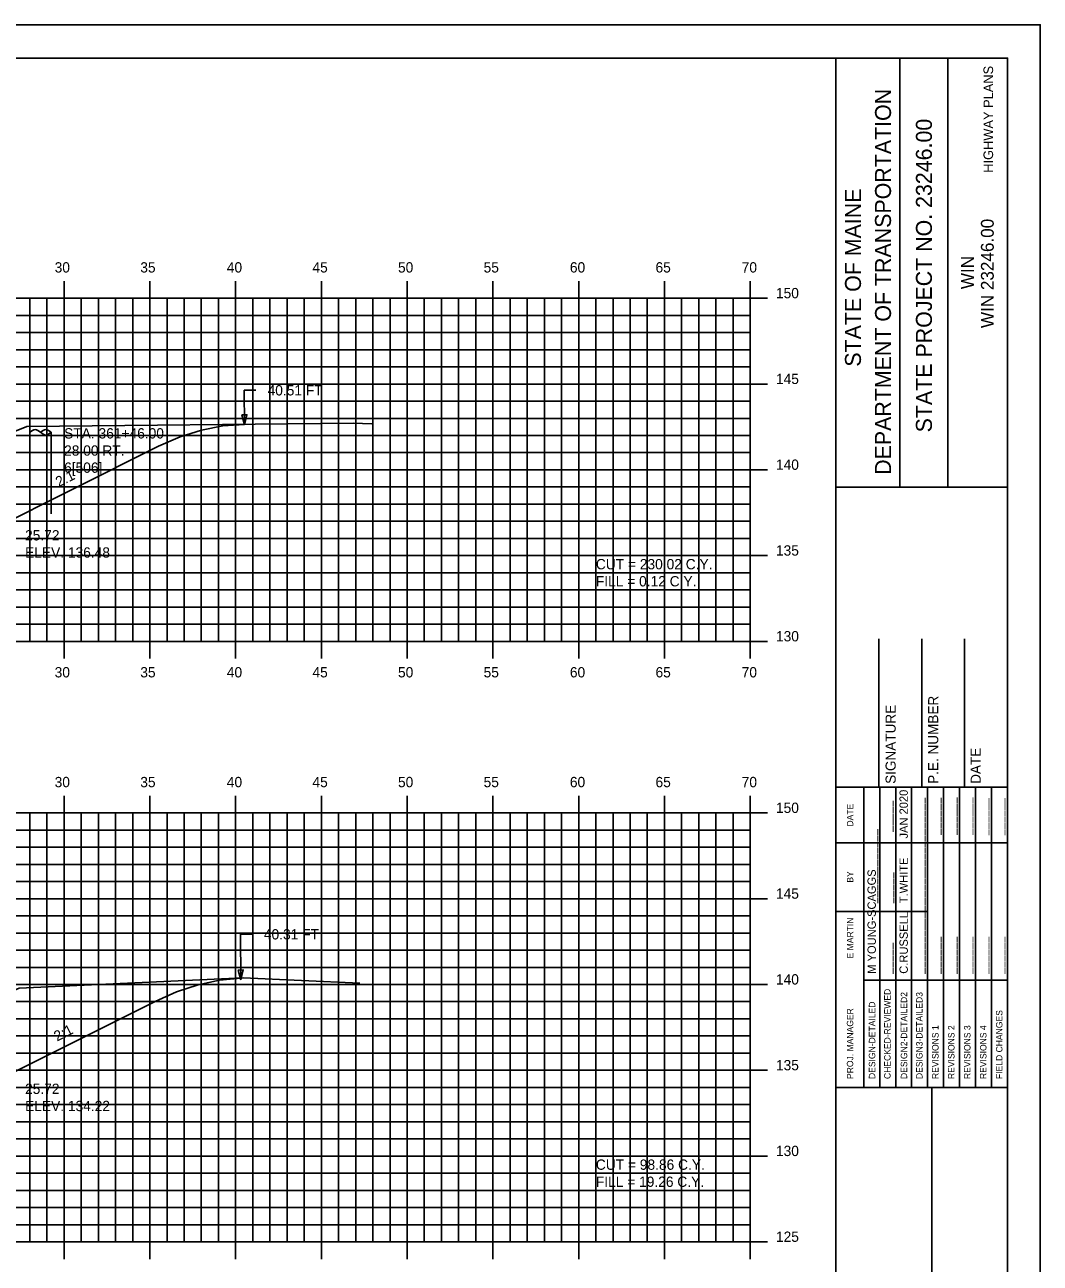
# Model space of a CAD drawing. Extents: x 1146525 to 1146695, y 608981 to 609091.
# Drawn here: x 1146635.4 to 1146694.6, y 609019.1 to 609091.3 of the extents above; entities that cross this region are included whole.
import ezdxf

# ---------------------------------------------------------------- set-up
doc = ezdxf.new("R2010")
doc.units = 0
for name, color, linetype in [('ANNOTATION', 7, 'Continuous'), ('BORDER', 7, 'Continuous'), ('D_Roadway_SlopeLines', 7, 'Continuous'), ('D_Text_Standard', 7, 'Continuous'), ('D_Utilities_Pole_Joint_Rt', 7, 'Continuous'), ('H_V ANNOTATION', 7, 'Continuous'), ('HIGHWAY_TITLE', 7, 'Continuous'), ('MAJOR', 7, 'Continuous'), ('MINOR', 7, 'Continuous'), ('PLOT BOUNDARY', 7, 'Continuous'), ('S_Roadway_Centerline', 7, 'Continuous')]:
    doc.layers.add(name, color=color, linetype=linetype)

msp = doc.modelspace()

# ---------------------------------------------------------------- linework, layer by layer
for points in [[(1146572.045, 609065.661), (1146573.295, 609065.521), (1146574.545, 609065.242), (1146575.795, 609064.824), (1146577.045, 609064.269), (1146581.947, 609061.818), (1146584.947, 609062.818), (1146592.67, 609065.392), (1146592.671, 609065.392), (1146596.671, 609065.552), (1146607.671, 609065.772), (1146618.671, 609065.552), (1146622.671, 609065.392), (1146630.395, 609062.818), (1146633.395, 609061.818), (1146643.18, 609066.71), (1146644.43, 609067.259), (1146645.68, 609067.654), (1146646.93, 609067.897), (1146648.18, 609067.986)], [(1146573.905, 609032.428), (1146575.155, 609032.306), (1146576.405, 609032.04), (1146577.655, 609031.631), (1146578.905, 609031.077), (1146581.947, 609029.556), (1146584.947, 609030.556), (1146592.67, 609033.131), (1146592.671, 609033.131), (1146596.671, 609033.291), (1146607.671, 609033.511), (1146618.671, 609033.291), (1146622.671, 609033.131), (1146630.395, 609030.556), (1146633.395, 609029.556), (1146642.977, 609034.348), (1146644.227, 609034.902), (1146645.477, 609035.313), (1146646.727, 609035.583), (1146647.977, 609035.71)]]:
    msp.add_lwpolyline(points)
at = {"layer": 'BORDER'}
for p, q in [((1146682.671, 608984.335), (1146682.671, 609089.335)), ((1146686.4, 609064.332), (1146686.4, 609089.332)), ((1146689.195, 609064.332), (1146689.195, 609089.332)), ((1146682.672, 609064.329), (1146692.671, 609064.329)), ((1146685.171, 609046.838), (1146685.171, 609055.485)), ((1146687.671, 609046.838), (1146687.671, 609055.485)), ((1146690.171, 609046.838), (1146690.171, 609055.485)), ((1146682.671, 609046.838), (1146692.671, 609046.838)), ((1146682.671, 609029.338), (1146692.671, 609029.338)), ((1146688.262, 608994.338), (1146688.262, 609029.338))]:
    msp.add_line(p, q, dxfattribs=at)
msp.add_lwpolyline([(1146532.671, 608984.335), (1146692.671, 608984.335), (1146692.671, 609089.335), (1146532.671, 609089.335)], close=True, dxfattribs=at)
for points in [[(1146684.286, 609043.588), (1146684.286, 609046.838)], [(1146685.219, 609029.341), (1146685.219, 609046.838)], [(1146686.151, 609046.838), (1146686.151, 609029.341)], [(1146687.082, 609029.341), (1146687.082, 609046.838)], [(1146688.014, 609029.341), (1146688.014, 609046.838)], [(1146688.946, 609029.341), (1146688.946, 609046.838)], [(1146689.877, 609029.341), (1146689.877, 609046.838)], [(1146690.809, 609029.341), (1146690.809, 609046.838)], [(1146691.741, 609029.341), (1146691.741, 609046.838)], [(1146684.287, 609029.341), (1146684.287, 609046.132)], [(1146682.671, 609043.588), (1146692.671, 609043.588)], [(1146682.671, 609039.588), (1146684.287, 609039.588)], [(1146684.286, 609039.588), (1146688.013, 609039.588)], [(1146684.286, 609035.588), (1146692.671, 609035.588)]]:
    msp.add_lwpolyline(points, dxfattribs=at)
at = {"layer": 'D_Roadway_SlopeLines'}
for points in [[(1146633.395, 609061.818), (1146643.18, 609066.71), (1146644.43, 609067.259), (1146645.68, 609067.654), (1146646.93, 609067.897), (1146648.18, 609067.986)], [(1146633.395, 609029.556), (1146642.977, 609034.348), (1146644.227, 609034.902), (1146645.477, 609035.313), (1146646.727, 609035.583), (1146647.977, 609035.71)]]:
    msp.add_lwpolyline(points, dxfattribs=at)
at = {"layer": 'D_Text_Standard'}
for points in [[(1146648.18, 609067.96), (1146648.174, 609069.97), (1146648.854, 609069.97)], [(1146647.977, 609035.598), (1146647.958, 609038.262), (1146648.638, 609038.262)]]:
    msp.add_lwpolyline(points, dxfattribs=at)
for points in [[(1146648.18, 609067.96), (1146648.033, 609068.542), (1146648.324, 609068.543)], [(1146647.977, 609035.598), (1146647.827, 609036.179), (1146648.119, 609036.181)]]:
    msp.add_lwpolyline(points, close=True, dxfattribs=at)
at = {"layer": 'D_Utilities_Pole_Joint_Rt'}
for p, q in [((1146635.671, 609067.521), (1146635.827, 609067.631)), ((1146635.671, 609062.763), (1146635.671, 609067.521)), ((1146636.14, 609067.631), (1146636.296, 609067.521)), ((1146636.452, 609067.631), (1146636.296, 609067.521)), ((1146636.296, 609067.521), (1146636.452, 609067.41)), ((1146636.921, 609067.521), (1146636.765, 609067.631)), ((1146636.765, 609067.41), (1146636.921, 609067.521)), ((1146636.921, 609062.763), (1146636.921, 609067.521))]:
    msp.add_line(p, q, dxfattribs=at)
for centre, start, end in [((1146635.984, 609067.411), 90, 125.26439), ((1146635.984, 609067.411), 54.73561, 90), ((1146636.609, 609067.411), 90, 125.26439), ((1146636.609, 609067.632), 234.73561, 270), ((1146636.609, 609067.411), 54.73561, 90), ((1146636.609, 609067.632), 270, 305.26439)]:
    msp.add_arc(centre, 0.271, start, end, dxfattribs=at)
at = {"layer": 'MAJOR'}
for p, q in [((1146637.671, 609076.337), (1146637.671, 609075.335)), ((1146642.671, 609076.337), (1146642.671, 609075.335)), ((1146647.671, 609076.337), (1146647.671, 609075.335)), ((1146652.671, 609076.337), (1146652.671, 609075.335)), ((1146657.671, 609076.337), (1146657.671, 609075.335)), ((1146662.671, 609076.337), (1146662.671, 609075.335)), ((1146667.671, 609076.337), (1146667.671, 609075.335)), ((1146672.671, 609076.337), (1146672.671, 609075.335)), ((1146677.671, 609076.337), (1146677.671, 609075.335)), ((1146537.671, 609075.335), (1146677.671, 609075.335)), ((1146537.671, 609075.335), (1146677.671, 609075.335)), ((1146637.671, 609055.335), (1146637.671, 609075.335)), ((1146642.671, 609055.335), (1146642.671, 609075.335)), ((1146647.671, 609055.335), (1146647.671, 609075.335)), ((1146652.671, 609055.335), (1146652.671, 609075.335)), ((1146657.671, 609055.335), (1146657.671, 609075.335)), ((1146662.671, 609055.335), (1146662.671, 609075.335)), ((1146667.671, 609055.335), (1146667.671, 609075.335)), ((1146672.671, 609055.335), (1146672.671, 609075.335)), ((1146678.673, 609075.335), (1146676.669, 609075.335)), ((1146677.671, 609055.335), (1146677.671, 609075.335)), ((1146677.671, 609055.335), (1146677.671, 609075.335)), ((1146537.671, 609070.335), (1146677.671, 609070.335)), ((1146678.673, 609070.335), (1146676.669, 609070.335)), ((1146537.671, 609065.335), (1146677.671, 609065.335)), ((1146678.673, 609065.335), (1146676.669, 609065.335)), ((1146537.671, 609060.335), (1146677.671, 609060.335)), ((1146678.673, 609060.335), (1146676.669, 609060.335)), ((1146537.671, 609055.335), (1146677.671, 609055.335)), ((1146537.671, 609055.335), (1146677.671, 609055.335)), ((1146637.671, 609054.333), (1146637.671, 609055.335)), ((1146642.671, 609054.333), (1146642.671, 609055.335)), ((1146647.671, 609054.333), (1146647.671, 609055.335)), ((1146652.671, 609054.333), (1146652.671, 609055.335)), ((1146657.671, 609054.333), (1146657.671, 609055.335)), ((1146662.671, 609054.333), (1146662.671, 609055.335)), ((1146667.671, 609054.333), (1146667.671, 609055.335)), ((1146672.671, 609054.333), (1146672.671, 609055.335)), ((1146678.673, 609055.335), (1146676.669, 609055.335)), ((1146677.671, 609054.333), (1146677.671, 609055.335)), ((1146637.671, 609046.337), (1146637.671, 609045.335)), ((1146642.671, 609046.337), (1146642.671, 609045.335)), ((1146647.671, 609046.337), (1146647.671, 609045.335)), ((1146652.671, 609046.337), (1146652.671, 609045.335)), ((1146657.671, 609046.337), (1146657.671, 609045.335)), ((1146662.671, 609046.337), (1146662.671, 609045.335)), ((1146667.671, 609046.337), (1146667.671, 609045.335)), ((1146672.671, 609046.337), (1146672.671, 609045.335)), ((1146677.671, 609046.337), (1146677.671, 609045.335)), ((1146537.671, 609045.335), (1146677.671, 609045.335)), ((1146537.671, 609045.335), (1146677.671, 609045.335)), ((1146637.671, 609020.335), (1146637.671, 609045.335)), ((1146642.671, 609020.335), (1146642.671, 609045.335)), ((1146647.671, 609020.335), (1146647.671, 609045.335)), ((1146652.671, 609020.335), (1146652.671, 609045.335)), ((1146657.671, 609020.335), (1146657.671, 609045.335)), ((1146662.671, 609020.335), (1146662.671, 609045.335)), ((1146667.671, 609020.335), (1146667.671, 609045.335)), ((1146672.671, 609020.335), (1146672.671, 609045.335)), ((1146678.673, 609045.335), (1146676.669, 609045.335)), ((1146677.671, 609020.335), (1146677.671, 609045.335)), ((1146677.671, 609020.335), (1146677.671, 609045.335)), ((1146537.671, 609040.335), (1146677.671, 609040.335)), ((1146678.673, 609040.335), (1146676.669, 609040.335)), ((1146537.671, 609035.335), (1146677.671, 609035.335)), ((1146678.673, 609035.335), (1146676.669, 609035.335)), ((1146537.671, 609030.335), (1146677.671, 609030.335)), ((1146678.673, 609030.335), (1146676.669, 609030.335)), ((1146537.671, 609025.335), (1146677.671, 609025.335)), ((1146678.673, 609025.335), (1146676.669, 609025.335)), ((1146537.671, 609020.335), (1146677.671, 609020.335)), ((1146537.671, 609020.335), (1146677.671, 609020.335)), ((1146637.671, 609019.333), (1146637.671, 609020.335)), ((1146642.671, 609019.333), (1146642.671, 609020.335)), ((1146647.671, 609019.333), (1146647.671, 609020.335)), ((1146652.671, 609019.333), (1146652.671, 609020.335)), ((1146657.671, 609019.333), (1146657.671, 609020.335)), ((1146662.671, 609019.333), (1146662.671, 609020.335)), ((1146667.671, 609019.333), (1146667.671, 609020.335)), ((1146672.671, 609019.333), (1146672.671, 609020.335)), ((1146678.673, 609020.335), (1146676.669, 609020.335)), ((1146677.671, 609019.333), (1146677.671, 609020.335))]:
    msp.add_line(p, q, dxfattribs=at)
at = {"layer": 'MINOR'}
for p, q in [((1146635.671, 609055.335), (1146635.671, 609075.335)), ((1146636.671, 609055.335), (1146636.671, 609075.335)), ((1146638.671, 609055.335), (1146638.671, 609075.335)), ((1146639.671, 609055.335), (1146639.671, 609075.335)), ((1146640.671, 609055.335), (1146640.671, 609075.335)), ((1146641.671, 609055.335), (1146641.671, 609075.335)), ((1146643.671, 609055.335), (1146643.671, 609075.335)), ((1146644.671, 609055.335), (1146644.671, 609075.335)), ((1146645.671, 609055.335), (1146645.671, 609075.335)), ((1146646.671, 609055.335), (1146646.671, 609075.335)), ((1146648.671, 609055.335), (1146648.671, 609075.335)), ((1146649.671, 609055.335), (1146649.671, 609075.335)), ((1146650.671, 609055.335), (1146650.671, 609075.335)), ((1146651.671, 609055.335), (1146651.671, 609075.335)), ((1146653.671, 609055.335), (1146653.671, 609075.335)), ((1146654.671, 609055.335), (1146654.671, 609075.335)), ((1146655.671, 609055.335), (1146655.671, 609075.335)), ((1146656.671, 609055.335), (1146656.671, 609075.335)), ((1146658.671, 609055.335), (1146658.671, 609075.335)), ((1146659.671, 609055.335), (1146659.671, 609075.335)), ((1146660.671, 609055.335), (1146660.671, 609075.335)), ((1146661.671, 609055.335), (1146661.671, 609075.335)), ((1146663.671, 609055.335), (1146663.671, 609075.335)), ((1146664.671, 609055.335), (1146664.671, 609075.335)), ((1146665.671, 609055.335), (1146665.671, 609075.335)), ((1146666.671, 609055.335), (1146666.671, 609075.335)), ((1146668.671, 609055.335), (1146668.671, 609075.335)), ((1146669.671, 609055.335), (1146669.671, 609075.335)), ((1146670.671, 609055.335), (1146670.671, 609075.335)), ((1146671.671, 609055.335), (1146671.671, 609075.335)), ((1146673.671, 609055.335), (1146673.671, 609075.335)), ((1146674.671, 609055.335), (1146674.671, 609075.335)), ((1146675.671, 609055.335), (1146675.671, 609075.335)), ((1146676.671, 609055.335), (1146676.671, 609075.335)), ((1146537.671, 609074.335), (1146677.671, 609074.335)), ((1146677.671, 609074.335), (1146676.669, 609074.335)), ((1146537.671, 609073.335), (1146677.671, 609073.335)), ((1146677.671, 609073.335), (1146676.669, 609073.335)), ((1146537.671, 609072.335), (1146677.671, 609072.335)), ((1146677.671, 609072.335), (1146676.669, 609072.335)), ((1146537.671, 609071.335), (1146677.671, 609071.335)), ((1146677.671, 609071.335), (1146676.669, 609071.335)), ((1146537.671, 609069.335), (1146677.671, 609069.335)), ((1146677.671, 609069.335), (1146676.669, 609069.335)), ((1146537.671, 609068.335), (1146677.671, 609068.335)), ((1146677.671, 609068.335), (1146676.669, 609068.335)), ((1146537.671, 609067.335), (1146677.671, 609067.335)), ((1146677.671, 609067.335), (1146676.669, 609067.335)), ((1146537.671, 609066.335), (1146677.671, 609066.335)), ((1146677.671, 609066.335), (1146676.669, 609066.335)), ((1146537.671, 609064.335), (1146677.671, 609064.335)), ((1146677.671, 609064.335), (1146676.669, 609064.335)), ((1146537.671, 609063.335), (1146677.671, 609063.335)), ((1146677.671, 609063.335), (1146676.669, 609063.335)), ((1146537.671, 609062.335), (1146677.671, 609062.335)), ((1146677.671, 609062.335), (1146676.669, 609062.335)), ((1146537.671, 609061.335), (1146677.671, 609061.335)), ((1146677.671, 609061.335), (1146676.669, 609061.335)), ((1146537.671, 609059.335), (1146677.671, 609059.335)), ((1146677.671, 609059.335), (1146676.669, 609059.335)), ((1146537.671, 609058.335), (1146677.671, 609058.335)), ((1146677.671, 609058.335), (1146676.669, 609058.335)), ((1146537.671, 609057.335), (1146677.671, 609057.335)), ((1146677.671, 609057.335), (1146676.669, 609057.335)), ((1146537.671, 609056.335), (1146677.671, 609056.335)), ((1146677.671, 609056.335), (1146676.669, 609056.335)), ((1146635.671, 609020.335), (1146635.671, 609045.335)), ((1146636.671, 609020.335), (1146636.671, 609045.335)), ((1146638.671, 609020.335), (1146638.671, 609045.335)), ((1146639.671, 609020.335), (1146639.671, 609045.335)), ((1146640.671, 609020.335), (1146640.671, 609045.335)), ((1146641.671, 609020.335), (1146641.671, 609045.335)), ((1146643.671, 609020.335), (1146643.671, 609045.335)), ((1146644.671, 609020.335), (1146644.671, 609045.335)), ((1146645.671, 609020.335), (1146645.671, 609045.335)), ((1146646.671, 609020.335), (1146646.671, 609045.335)), ((1146648.671, 609020.335), (1146648.671, 609045.335)), ((1146649.671, 609020.335), (1146649.671, 609045.335)), ((1146650.671, 609020.335), (1146650.671, 609045.335)), ((1146651.671, 609020.335), (1146651.671, 609045.335)), ((1146653.671, 609020.335), (1146653.671, 609045.335)), ((1146654.671, 609020.335), (1146654.671, 609045.335)), ((1146655.671, 609020.335), (1146655.671, 609045.335)), ((1146656.671, 609020.335), (1146656.671, 609045.335)), ((1146658.671, 609020.335), (1146658.671, 609045.335)), ((1146659.671, 609020.335), (1146659.671, 609045.335)), ((1146660.671, 609020.335), (1146660.671, 609045.335)), ((1146661.671, 609020.335), (1146661.671, 609045.335)), ((1146663.671, 609020.335), (1146663.671, 609045.335)), ((1146664.671, 609020.335), (1146664.671, 609045.335)), ((1146665.671, 609020.335), (1146665.671, 609045.335)), ((1146666.671, 609020.335), (1146666.671, 609045.335)), ((1146668.671, 609020.335), (1146668.671, 609045.335)), ((1146669.671, 609020.335), (1146669.671, 609045.335)), ((1146670.671, 609020.335), (1146670.671, 609045.335)), ((1146671.671, 609020.335), (1146671.671, 609045.335)), ((1146673.671, 609020.335), (1146673.671, 609045.335)), ((1146674.671, 609020.335), (1146674.671, 609045.335)), ((1146675.671, 609020.335), (1146675.671, 609045.335)), ((1146676.671, 609020.335), (1146676.671, 609045.335)), ((1146537.671, 609044.335), (1146677.671, 609044.335)), ((1146677.671, 609044.335), (1146676.669, 609044.335)), ((1146537.671, 609043.335), (1146677.671, 609043.335)), ((1146677.671, 609043.335), (1146676.669, 609043.335)), ((1146537.671, 609042.335), (1146677.671, 609042.335)), ((1146677.671, 609042.335), (1146676.669, 609042.335)), ((1146537.671, 609041.335), (1146677.671, 609041.335)), ((1146677.671, 609041.335), (1146676.669, 609041.335)), ((1146537.671, 609039.335), (1146677.671, 609039.335)), ((1146677.671, 609039.335), (1146676.669, 609039.335)), ((1146537.671, 609038.335), (1146677.671, 609038.335)), ((1146677.671, 609038.335), (1146676.669, 609038.335)), ((1146537.671, 609037.335), (1146677.671, 609037.335)), ((1146677.671, 609037.335), (1146676.669, 609037.335)), ((1146537.671, 609036.335), (1146677.671, 609036.335)), ((1146677.671, 609036.335), (1146676.669, 609036.335)), ((1146537.671, 609034.335), (1146677.671, 609034.335)), ((1146677.671, 609034.335), (1146676.669, 609034.335)), ((1146537.671, 609033.335), (1146677.671, 609033.335)), ((1146677.671, 609033.335), (1146676.669, 609033.335)), ((1146537.671, 609032.335), (1146677.671, 609032.335)), ((1146677.671, 609032.335), (1146676.669, 609032.335)), ((1146537.671, 609031.335), (1146677.671, 609031.335)), ((1146677.671, 609031.335), (1146676.669, 609031.335)), ((1146537.671, 609029.335), (1146677.671, 609029.335)), ((1146677.671, 609029.335), (1146676.669, 609029.335)), ((1146537.671, 609028.335), (1146677.671, 609028.335)), ((1146677.671, 609028.335), (1146676.669, 609028.335)), ((1146537.671, 609027.335), (1146677.671, 609027.335)), ((1146677.671, 609027.335), (1146676.669, 609027.335)), ((1146537.671, 609026.335), (1146677.671, 609026.335)), ((1146677.671, 609026.335), (1146676.669, 609026.335)), ((1146537.671, 609024.335), (1146677.671, 609024.335)), ((1146677.671, 609024.335), (1146676.669, 609024.335)), ((1146537.671, 609023.335), (1146677.671, 609023.335)), ((1146677.671, 609023.335), (1146676.669, 609023.335)), ((1146537.671, 609022.335), (1146677.671, 609022.335)), ((1146677.671, 609022.335), (1146676.669, 609022.335)), ((1146537.671, 609021.335), (1146677.671, 609021.335)), ((1146677.671, 609021.335), (1146676.669, 609021.335))]:
    msp.add_line(p, q, dxfattribs=at)
at = {"layer": 'PLOT BOUNDARY'}
msp.add_lwpolyline([(1146524.578, 608981.276), (1146694.578, 608981.276), (1146694.578, 609091.276), (1146524.578, 609091.276)], close=True, dxfattribs=at)
at = {"layer": 'S_Roadway_Centerline'}
for points in [[(1146555.658, 609066.541), (1146562.215, 609066.221), (1146582.411, 609065.07), (1146583.316, 609064.912), (1146587.853, 609063.497), (1146588.571, 609063.642), (1146593.356, 609064.948), (1146593.601, 609064.956), (1146595.56, 609064.969), (1146601.488, 609065.115), (1146606.926, 609065.194), (1146612.815, 609065.044), (1146617.656, 609064.926), (1146621.703, 609064.693), (1146621.82, 609064.681), (1146621.879, 609064.655), (1146624.765, 609063.492), (1146625.761, 609063.915), (1146635.495, 609067.854), (1146654.514, 609068.052), (1146655.612, 609068.025)], [(1146557.189, 609033.149), (1146565.05, 609032.785), (1146581.825, 609032.109), (1146584.311, 609031.657), (1146589.374, 609030.827), (1146592.033, 609031.484), (1146593.468, 609031.837), (1146594.03, 609031.88), (1146595.014, 609031.905), (1146600.278, 609032.092), (1146606.448, 609032.182), (1146612.282, 609032.042), (1146617.286, 609031.872), (1146619.517, 609031.64), (1146621.574, 609031.449), (1146622.756, 609030.931), (1146624.182, 609030.468), (1146629.549, 609032.75), (1146635.043, 609035.129), (1146648.103, 609035.716), (1146654.911, 609035.417)]]:
    msp.add_lwpolyline(points, dxfattribs=at)

# ---------------------------------------------------------------- texts
at = {"layer": 'ANNOTATION'}
for p in [(1146637.36, 609064.318), (1146637.259, 609032.006)]:
    msp.add_text('2:1', height=0.6, rotation=26.56505, dxfattribs=at).set_placement(p)
at = {"layer": 'BORDER'}
for s, height, p in [('DEPARTMENT OF TRANSPORTATION', 0.93176, (1146685.878, 609065.041)), ('STATE PROJECT NO. 23246.00', 0.93176, (1146688.263, 609067.517)), ('STATE OF MAINE', 0.93176, (1146684.127, 609071.347)), ('WIN 23246.00', 0.74527, (1146691.867, 609073.596)), ('WIN', 0.7453, (1146690.708, 609075.865)), ('SIGNATURE', 0.5906, (1146686.152, 609047.03)), ('P.E. NUMBER', 0.59055, (1146688.632, 609047.03)), ('DATE', 0.5906, (1146691.113, 609047.03)), ('JAN 2020', 0.4845, (1146686.858, 609043.843)), ('DATE', 0.3714, (1146683.676, 609044.544)), ('_____', 0.4845, (1146685.889, 609044.243)), ('______', 0.4845, (1146687.752, 609044.063)), ('______', 0.4845, (1146688.684, 609044.065)), ('______', 0.4845, (1146689.616, 609044.067)), ('______', 0.4845, (1146690.547, 609044.067)), ('______', 0.4845, (1146691.479, 609044.036)), ('______', 0.4845, (1146692.411, 609044.036)), ('____________', 0.48455, (1146684.994, 609040.073)), ('____________', 0.48455, (1146687.752, 609040.073)), ('T.WHITE', 0.4845, (1146686.858, 609040.073)), ('BY', 0.3714, (1146683.676, 609041.273)), ('M YOUNG-SCAGGS', 0.48455, (1146684.994, 609035.961)), ('_____', 0.4845, (1146685.926, 609040.073)), ('____________', 0.48455, (1146687.752, 609035.961)), ('C.RUSSELL', 0.4845, (1146686.858, 609035.961)), ('E MARTIN', 0.3727, (1146683.676, 609036.855)), ('_____', 0.4845, (1146685.889, 609035.961)), ('______', 0.4845, (1146688.684, 609035.961)), ('______', 0.4845, (1146689.616, 609035.961)), ('______', 0.4845, (1146690.547, 609035.961)), ('______', 0.4845, (1146691.479, 609035.961)), ('______', 0.4845, (1146692.411, 609035.961)), ('CHECKED-REVIEWED', 0.37275, (1146685.852, 609029.826)), ('DESIGN2-DETAILED2', 0.37275, (1146686.821, 609029.826)), ('DESIGN3-DETAILED3', 0.37275, (1146687.716, 609029.826)), ('DESIGN-DETAILED', 0.37275, (1146684.958, 609029.826)), ('PROJ. MANAGER', 0.37275, (1146683.676, 609029.826)), ('FIELD CHANGES', 0.37275, (1146692.374, 609029.826)), ('REVISIONS 1', 0.37275, (1146688.648, 609029.826)), ('REVISIONS 2', 0.37275, (1146689.579, 609029.826)), ('REVISIONS 3', 0.37275, (1146690.511, 609029.826)), ('REVISIONS 4', 0.37275, (1146691.443, 609029.826))]:
    msp.add_text(s, height=height, rotation=90, dxfattribs=at).set_placement(p)
at = {"layer": 'D_Text_Standard'}
for s, p in [('40.51 FT', (1146649.534, 609069.67)), ('STA. 361+46.00', (1146637.671, 609067.161)), ('28.00 RT.', (1146637.671, 609066.159)), ('6[506] ', (1146637.671, 609065.163)), ('25.72', (1146635.395, 609061.218)), ('ELEV. 136.48', (1146635.395, 609060.216)), ('CUT = 230.02 C.Y.', (1146668.671, 609059.535)), ('FILL = 0.12 C.Y.', (1146668.671, 609058.539)), ('40.31 FT', (1146649.318, 609037.962)), ('25.72', (1146635.395, 609028.956)), ('ELEV. 134.22', (1146635.395, 609027.954)), ('CUT = 98.86 C.Y.', (1146668.671, 609024.535)), ('FILL = 19.26 C.Y.', (1146668.671, 609023.539))]:
    msp.add_text(s, height=0.6, dxfattribs=at).set_placement(p)
at = {"layer": 'H_V ANNOTATION'}
for s, p in [('30', (1146637.12, 609076.835)), ('35', (1146642.112, 609076.835)), ('40', (1146647.157, 609076.835)), ('45', (1146652.149, 609076.835)), ('50', (1146657.136, 609076.835)), ('55', (1146662.128, 609076.835)), ('60', (1146667.157, 609076.835)), ('65', (1146672.149, 609076.835)), ('70', (1146677.173, 609076.835)), ('150', (1146679.171, 609075.335)), ('145', (1146679.171, 609070.335)), ('140', (1146679.171, 609065.335)), ('135', (1146679.171, 609060.335)), ('130', (1146679.171, 609055.335)), ('30', (1146637.12, 609053.235)), ('35', (1146642.112, 609053.235)), ('40', (1146647.157, 609053.235)), ('45', (1146652.149, 609053.235)), ('50', (1146657.136, 609053.235)), ('55', (1146662.128, 609053.235)), ('60', (1146667.157, 609053.235)), ('65', (1146672.149, 609053.235)), ('70', (1146677.173, 609053.235)), ('30', (1146637.12, 609046.835)), ('35', (1146642.112, 609046.835)), ('40', (1146647.157, 609046.835)), ('45', (1146652.149, 609046.835)), ('50', (1146657.136, 609046.835)), ('55', (1146662.128, 609046.835)), ('60', (1146667.157, 609046.835)), ('65', (1146672.149, 609046.835)), ('70', (1146677.173, 609046.835)), ('150', (1146679.171, 609045.335)), ('145', (1146679.171, 609040.335)), ('140', (1146679.171, 609035.335)), ('135', (1146679.171, 609030.335)), ('130', (1146679.171, 609025.335)), ('125', (1146679.171, 609020.335))]:
    msp.add_text(s, height=0.6, dxfattribs=at).set_placement(p)
at = {"layer": 'HIGHWAY_TITLE'}
msp.add_text('HIGHWAY PLANS', height=0.55901, rotation=90, dxfattribs=at).set_placement((1146691.83, 609082.65))

doc.saveas('drawing.dxf')
